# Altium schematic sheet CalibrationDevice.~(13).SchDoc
size A2; SPICEModelCacheJMJTSHEM: <root> / <DocumentId>JMJTSHEM</DocumentId> / <CacheFrame Number="0"> / <Model Name="cap" Kind="MDL"> / <Text>*Default semiconductor capacitor / .MODEL CAP C()</Text> / </Model> / </CacheFrame> / </root>
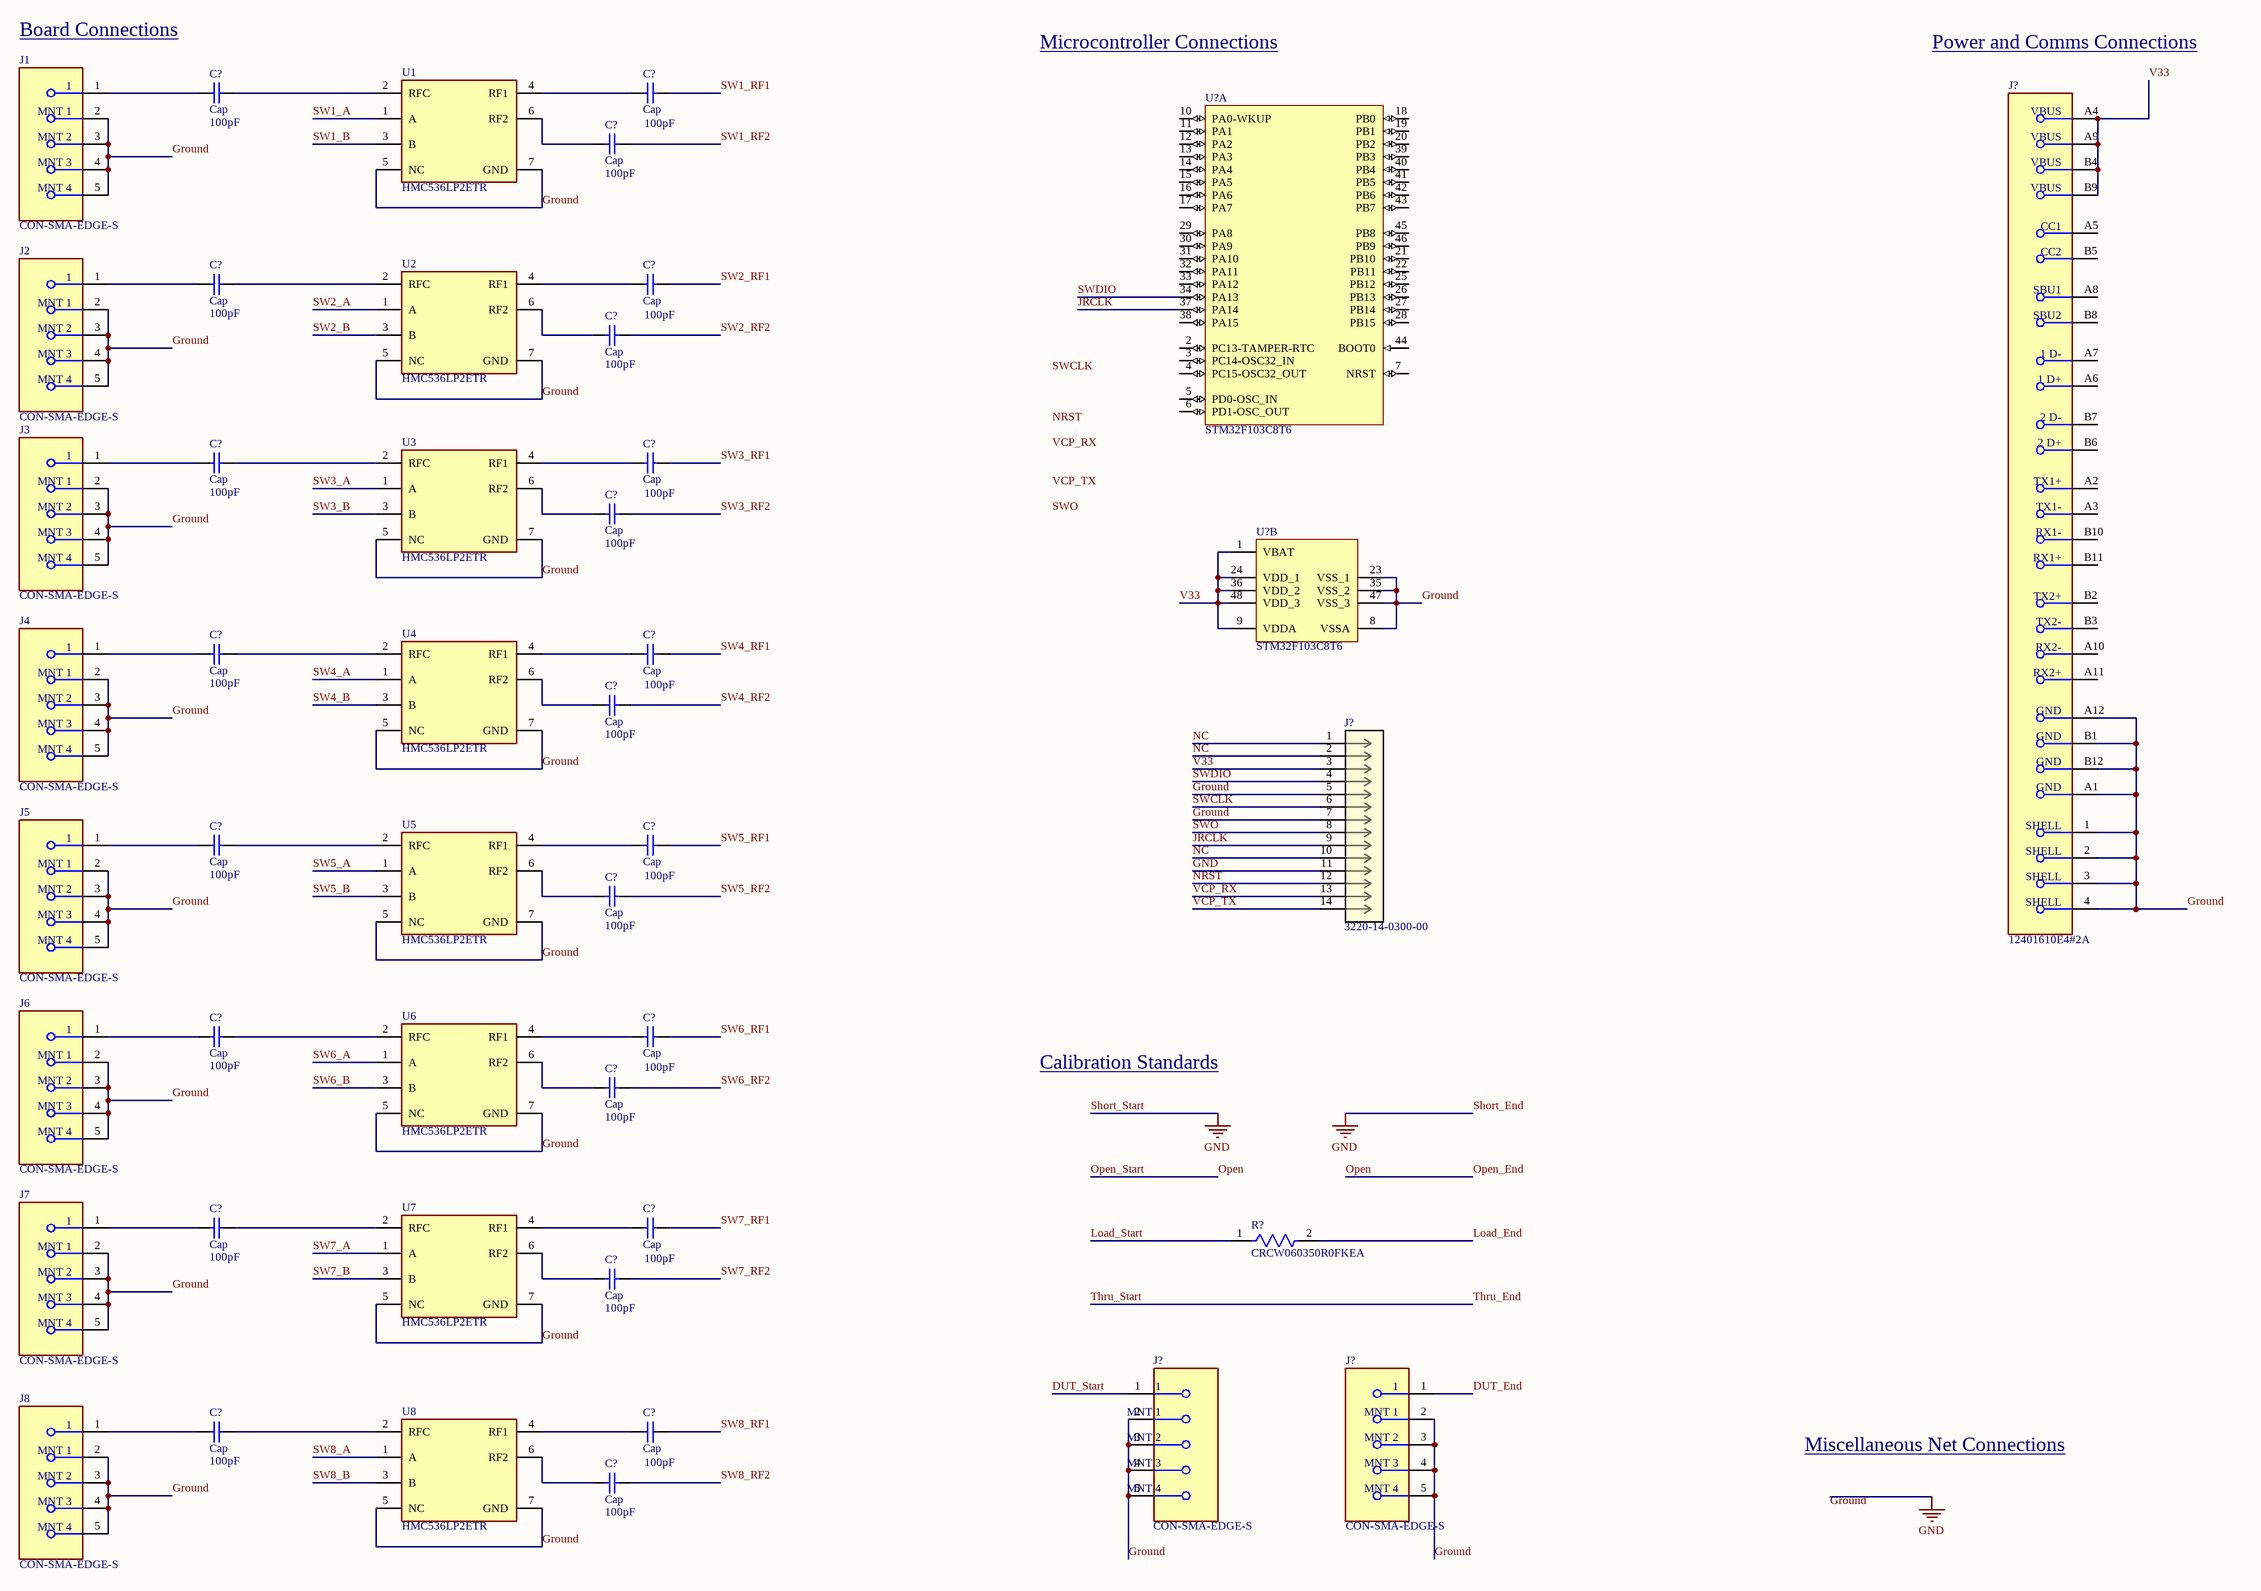
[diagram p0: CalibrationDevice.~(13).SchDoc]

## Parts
(Parts that share a designator on the sheet are numbered #1, #2 ... from top to bottom, then left to right.)
C?#1  Cap  value 100pF  [RAD-0.3]
C?#2  Cap  value 100pF  [RAD-0.3]
C?#3  Cap  value 100pF  [RAD-0.3]
C?#4  Cap  value 100pF  [RAD-0.3]
C?#5  Cap  value 100pF  [RAD-0.3]
C?#6  Cap  value 100pF  [RAD-0.3]
C?#7  Cap  value 100pF  [RAD-0.3]
C?#8  Cap  value 100pF  [RAD-0.3]
C?#9  Cap  value 100pF  [RAD-0.3]
C?#10  Cap  value 100pF  [RAD-0.3]
C?#11  Cap  value 100pF  [RAD-0.3]
C?#12  Cap  value 100pF  [RAD-0.3]
C?#13  Cap  value 100pF  [RAD-0.3]
C?#14  Cap  value 100pF  [RAD-0.3]
C?#15  Cap  value 100pF  [RAD-0.3]
C?#16  Cap  value 100pF  [RAD-0.3]
C?#17  Cap  value 100pF  [RAD-0.3]
C?#18  Cap  value 100pF  [RAD-0.3]
C?#19  Cap  value 100pF  [RAD-0.3]
C?#20  Cap  value 100pF  [RAD-0.3]
C?#21  Cap  value 100pF  [RAD-0.3]
C?#22  Cap  value 100pF  [RAD-0.3]
C?#23  Cap  value 100pF  [RAD-0.3]
C?#24  Cap  value 100pF  [RAD-0.3]
J1  CON-SMA-EDGE-S  [FP-CON-SMA-EDGE-S-MFG]
J2  CON-SMA-EDGE-S  [FP-CON-SMA-EDGE-S-MFG]
J3  CON-SMA-EDGE-S  [FP-CON-SMA-EDGE-S-MFG]
J4  CON-SMA-EDGE-S  [FP-CON-SMA-EDGE-S-MFG]
J5  CON-SMA-EDGE-S  [FP-CON-SMA-EDGE-S-MFG]
J6  CON-SMA-EDGE-S  [FP-CON-SMA-EDGE-S-MFG]
J7  CON-SMA-EDGE-S  [FP-CON-SMA-EDGE-S-MFG]
J8  CON-SMA-EDGE-S  [FP-CON-SMA-EDGE-S-MFG]
J?#1  12401610E4#2A  [FP-12401610E4#2A-MFG]
J?#2  3220-14-0300-00  [CONN_3220-14-0300-00_CNC]
J?#3  CON-SMA-EDGE-S  [FP-CON-SMA-EDGE-S-MFG]
J?#4  CON-SMA-EDGE-S  [FP-CON-SMA-EDGE-S-MFG]
R?  CRCW060350R0FKEA  [FP-CRCW0603-e3-MFG]
U1  HMC536LP2ETR  [FP-LP2E-MFG]
U2  HMC536LP2ETR  [FP-LP2E-MFG]
U3  HMC536LP2ETR  [FP-LP2E-MFG]
U4  HMC536LP2ETR  [FP-LP2E-MFG]
U5  HMC536LP2ETR  [FP-LP2E-MFG]
U6  HMC536LP2ETR  [FP-LP2E-MFG]
U7  HMC536LP2ETR  [FP-LP2E-MFG]
U8  HMC536LP2ETR  [FP-LP2E-MFG]
U?#1  STM32F103C8T6  [STM-LQFP48_L]  (part A of 2)
U?#2  STM32F103C8T6  [STM-LQFP48_L]  (part B of 2)

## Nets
GND: J?#2.11  [also labelled Short_End, Short_Start]
DUT_End: J?#4.1
DUT_Start: J?#3.1
Ground: J1.2(MNT_1) J1.3(MNT_2) J1.4(MNT_3) J1.5(MNT_4) J2.2(MNT_1) J2.3(MNT_2) J2.4(MNT_3) J2.5(MNT_4) J3.2(MNT_1) J3.3(MNT_2) J3.4(MNT_3) J3.5(MNT_4) J4.2(MNT_1) J4.3(MNT_2) J4.4(MNT_3) J4.5(MNT_4) J5.2(MNT_1) J5.3(MNT_2) J5.4(MNT_3) J5.5(MNT_4) J6.2(MNT_1) J6.3(MNT_2) J6.4(MNT_3) J6.5(MNT_4) J7.2(MNT_1) J7.3(MNT_2) J7.4(MNT_3) J7.5(MNT_4) J8.2(MNT_1) J8.3(MNT_2) J8.4(MNT_3) J8.5(MNT_4) J?#1.1(SHELL) J?#1.2(SHELL) J?#1.3(SHELL) J?#1.4(SHELL) J?#1.A1(GND) J?#1.A12(GND) J?#1.B1(GND) J?#1.B12(GND) J?#2.5 J?#2.7 J?#3.2(MNT_1) J?#3.3(MNT_2) J?#3.4(MNT_3) J?#3.5(MNT_4) J?#4.2(MNT_1) J?#4.3(MNT_2) J?#4.4(MNT_3) J?#4.5(MNT_4) U1.5(NC) U1.7(GND) U2.5(NC) U2.7(GND) U3.5(NC) U3.7(GND) U4.5(NC) U4.7(GND) U5.5(NC) U5.7(GND) U6.5(NC) U6.7(GND) U7.5(NC) U7.7(GND) U8.5(NC) U8.7(GND) U?#2.8(VSSA) U?#2.23(VSS_1) U?#2.35(VSS_2) U?#2.47(VSS_3)
JRCLK: J?#2.9 U?#1.37(PA14)
Load_End: R?.2
Load_Start: R?.1
NC: J?#2.1 J?#2.2 J?#2.10
NRST: J?#2.12
SW1_A: U1.1(A)
SW1_B: U1.3(B)
SW1_RF1: C?#2.2
SW1_RF2: C?#3.2
SW2_A: U2.1(A)
SW2_B: U2.3(B)
SW2_RF1: C?#5.2
SW2_RF2: C?#6.2
SW3_A: U3.1(A)
SW3_B: U3.3(B)
SW3_RF1: C?#8.2
SW3_RF2: C?#9.2
SW4_A: U4.1(A)
SW4_B: U4.3(B)
SW4_RF1: C?#11.2
SW4_RF2: C?#12.2
SW5_A: U5.1(A)
SW5_B: U5.3(B)
SW5_RF1: C?#14.2
SW5_RF2: C?#15.2
SW6_A: U6.1(A)
SW6_B: U6.3(B)
SW6_RF1: C?#17.2
SW6_RF2: C?#18.2
SW7_A: U7.1(A)
SW7_B: U7.3(B)
SW7_RF1: C?#20.2
SW7_RF2: C?#21.2
SW8_A: U8.1(A)
SW8_B: U8.3(B)
SW8_RF1: C?#23.2
SW8_RF2: C?#24.2
SWCLK: J?#2.6
SWDIO: J?#2.4 U?#1.34(PA13)
SWO: J?#2.8
V33: J?#1.A4(VBUS) J?#1.A9(VBUS) J?#1.B4(VBUS) J?#1.B9(VBUS) J?#2.3 U?#2.1(VBAT) U?#2.9(VDDA) U?#2.24(VDD_1) U?#2.36(VDD_2) U?#2.48(VDD_3)
VCP_RX: J?#2.13
VCP_TX: J?#2.14
NetC?#1_1: C?#1.1 J1.1
NetC?#1_2: C?#1.2 U1.2(RFC)
NetC?#2_1: C?#2.1 U1.4(RF1)
NetC?#3_1: C?#3.1 U1.6(RF2)
NetC?#4_1: C?#4.1 J2.1
NetC?#4_2: C?#4.2 U2.2(RFC)
NetC?#5_1: C?#5.1 U2.4(RF1)
NetC?#6_1: C?#6.1 U2.6(RF2)
NetC?#7_1: C?#7.1 J3.1
NetC?#7_2: C?#7.2 U3.2(RFC)
NetC?#8_1: C?#8.1 U3.4(RF1)
NetC?#9_1: C?#9.1 U3.6(RF2)
NetC?#10_1: C?#10.1 J4.1
NetC?#10_2: C?#10.2 U4.2(RFC)
NetC?#11_1: C?#11.1 U4.4(RF1)
NetC?#12_1: C?#12.1 U4.6(RF2)
NetC?#13_1: C?#13.1 J5.1
NetC?#13_2: C?#13.2 U5.2(RFC)
NetC?#14_1: C?#14.1 U5.4(RF1)
NetC?#15_1: C?#15.1 U5.6(RF2)
NetC?#16_1: C?#16.1 J6.1
NetC?#16_2: C?#16.2 U6.2(RFC)
NetC?#17_1: C?#17.1 U6.4(RF1)
NetC?#18_1: C?#18.1 U6.6(RF2)
NetC?#19_1: C?#19.1 J7.1
NetC?#19_2: C?#19.2 U7.2(RFC)
NetC?#20_1: C?#20.1 U7.4(RF1)
NetC?#21_1: C?#21.1 U7.6(RF2)
NetC?#22_1: C?#22.1 J8.1
NetC?#22_2: C?#22.2 U8.2(RFC)
NetC?#23_1: C?#23.1 U8.4(RF1)
NetC?#24_1: C?#24.1 U8.6(RF2)

Not connected (* = marked no-connect by the designer): J?#1 A2(TX1+) A3(TX1-) A5(CC1) A6(1_D+) A7(1_D-) A8(SBU1) A10(RX2-) A11(RX2+) B2(TX2+) B3(TX2-) B5(CC2) B6(2_D+) B7(2_D-) B8(SBU2) B10(RX1-) B11(RX1+); U?#1 2(PC13-TAMPER-RTC) 3(PC14-OSC32_IN) 4(PC15-OSC32_OUT) 5(PD0-OSC_IN) 6(PD1-OSC_OUT) 7(NRST) 10(PA0-WKUP) 11(PA1) 12(PA2) 13(PA3) 14(PA4) 15(PA5) 16(PA6) 17(PA7) 18(PB0) 19(PB1) 20(PB2) 21(PB10) 22(PB11) 25(PB12) 26(PB13) 27(PB14) 28(PB15) 29(PA8) 30(PA9) 31(PA10) 32(PA11) 33(PA12) 38(PA15) 39(PB3) 40(PB4) 41(PB5) 42(PB6) 43(PB7) 44(BOOT0) 45(PB8) 46(PB9)

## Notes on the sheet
- Board Connections
- Microcontroller Connections
- Power and Comms Connections
- Calibration Standards
- Miscellaneous Net Connections
- Labels drawn without touching a wire or pin: Ground, NRST, SWCLK, SWO, VCP_RX, VCP_TX

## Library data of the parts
C?#1-C?#24 = Cap: Capacitor
J1-J8 J?#3 J?#4 = CMP-204357-000001-1: CONN SMA JACK STR EDGE MNT; Manufacturer: RF Solutions Ltd.; Impedance: 50Ω; Conn Orientation: Right Angle; Is Female: yes; Number Of Contacts: 1; Frequency: 18GHz; Shielding: true
J?#1 = CMP-15126-126516878-1: 12401610E4#2A Conn USB Type C RCP 24 POS 0.5mm Solder RA SMD 24 Terminal 1 Port Automotive; Gender: Receptacle; USB Standard: USB 3.1; Number of Contacts: 24; Current Rating: 5A
J?#2 = 3220-14-0300-00: No Description Available; Mfr_Name: CNC Tech
R? = CMP-2000-03436-2: RES Thick Film, 50Ω, 1%, 0.1W, 100ppm/°C, 0603; Voltage Rating (DC): 75V; Resistance: 50R; Power Rating: 100mW
U1-U8 = CMP-09141-000138-1: IC RF SWITCH SPDT 6GHZ 6DFN; P1dB: 33dBm; Impedance: 50R; Max Power Dissipation: 860mW; Insertion Loss: 0.6dB; IIP3: 52dBm
U?#1 U?#2 = CMP-0237-00215-3: ARM Cortex-M3 32-bit MCU, 64 KB Flash, 20 KB Internal RAM, 37 I/Os, 48-pin LQFP, -40 to 85 degC, Tray; Supply Voltage(Vcc) min (V): 2; Internal RAM Size (kB): 20; FLASH Size (Prog) (kB): 64; A/D Converter: 2x12-bit (10 Channel); I/Os (High Current): 37; Operating Frequency(F) (Processor speed) (MHz): 72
